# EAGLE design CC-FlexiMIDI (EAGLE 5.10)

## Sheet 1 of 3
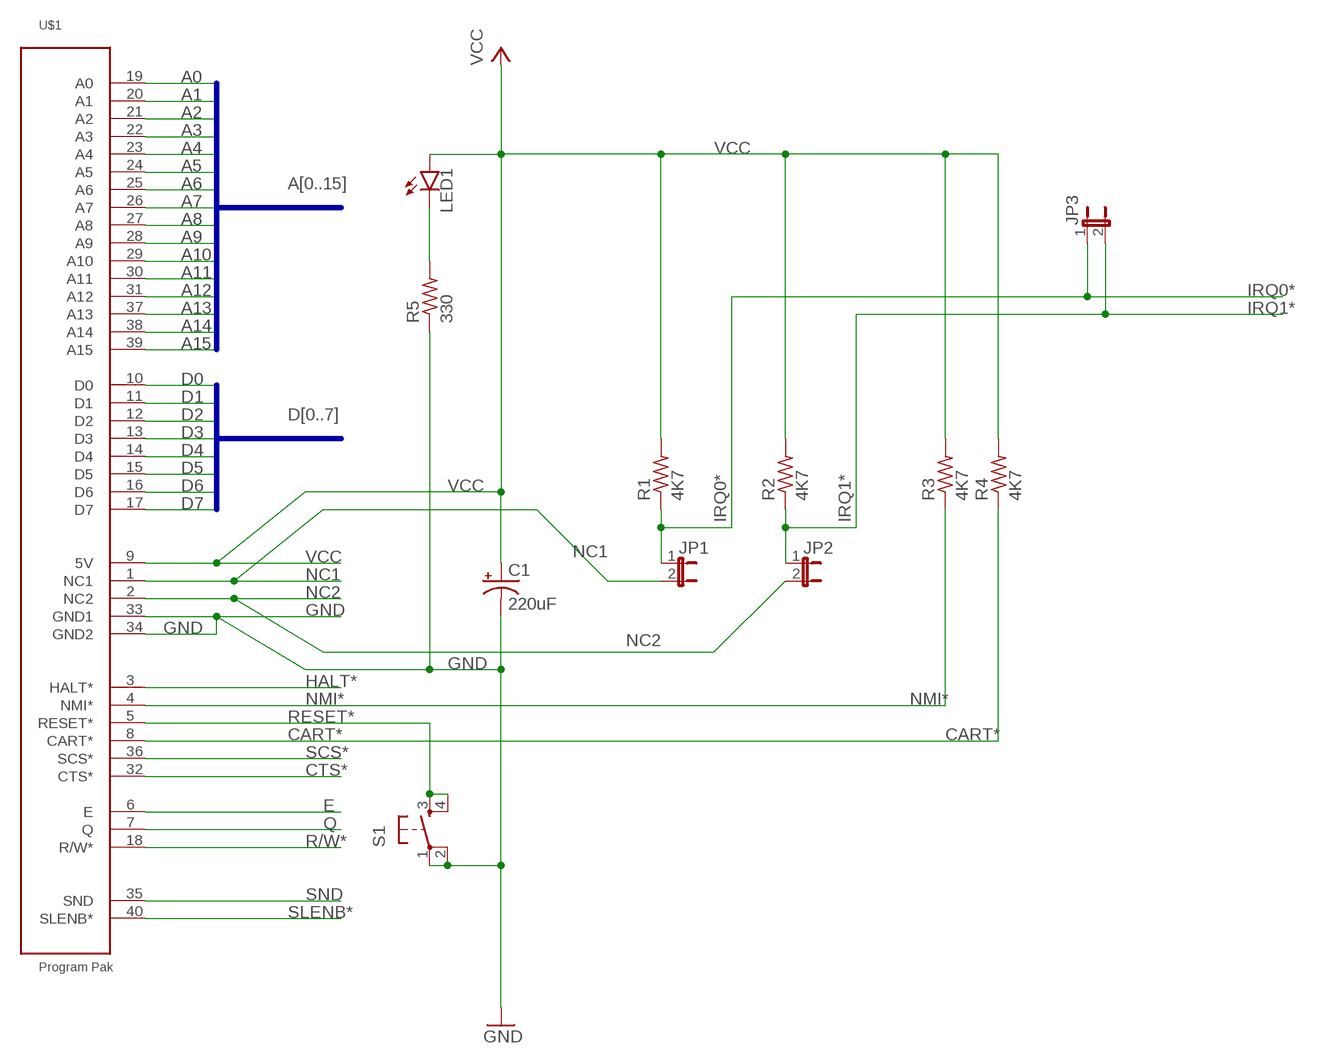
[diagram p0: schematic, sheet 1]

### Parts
C1  220uF  SPARKFUN_CAP_POLPTH1  [SPARKFUN_CPOL-RADIAL-100UF-25V]
JP1  JP1E  [JP1]
JP2  JP1E  [JP1]
JP3  JP1E  [JP1]
LED1  RED  LED5MM  [LED5MM]
R1  4K7  R-US_0207/7  [0207/7]
R2  4K7  R-US_0207/7  [0207/7]
R3  4K7  R-US_0207/7  [0207/7]
R4  4K7  R-US_0207/7  [0207/7]
R5  330  R-US_0207/7  [0207/7]
S1  RESET  TAC_SWITCHPTH  [TACTILE-PTH]
U$1  Program Pak  SERIALTECH_COCO_CARTRIDGE  [SERIALTECH_EDGE40]

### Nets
A0: U$1.19(A0) ; also sheet 3
A1: U$1.20(A1) ; also sheet 3
A2: U$1.21(A2) ; also sheet 3
A3: U$1.22(A3) ; also sheet 2
A4: U$1.23(A4) ; also sheet 2
A5: U$1.24(A5) ; also sheet 3
A6: U$1.25(A6) ; also sheet 3
A7: U$1.26(A7) ; also sheet 2
A8: U$1.27(A8) ; also sheet 3
A9: U$1.28(A9) ; also sheet 3
A10: U$1.29(A10) ; also sheet 3
A11: U$1.30(A11) ; also sheet 3
A12: U$1.31(A12) ; also sheet 3
A13: U$1.37(A13) ; also sheet 3
A14: U$1.38(A14) ; also sheet 3
A15: U$1.39(A15) ; also sheet 3
CART*: R4.1 U$1.8(CART*) ; also sheet 3
CTS*: U$1.32(CTS*)
D0: U$1.10(D0) ; also sheet 3
D1: U$1.11(D1) ; also sheet 3
D2: U$1.12(D2) ; also sheet 3
D3: U$1.13(D3) ; also sheet 3
D4: U$1.14(D4) ; also sheet 3
D5: U$1.15(D5) ; also sheet 3
D6: U$1.16(D6) ; also sheet 3
D7: U$1.17(D7) ; also sheet 3
E: U$1.6(E) ; also sheet 3
GND [power]: C1.2(-) R5.1 S1.1 S1.2 U$1.33(GND1) U$1.34(GND2) ; also sheet 2,3
HALT*: U$1.3(HALT*)
IRQ0*: JP1.1 JP3.1 R1.1 ; also sheet 3
IRQ1*: JP2.1 JP3.2 R2.1 ; also sheet 3
N$2: LED1.K(CATHODE) R5.2
NC1: JP1.2 U$1.1(NC1)
NC2: JP2.2 U$1.2(NC2)
NMI*: R3.1 U$1.4(NMI*) ; also sheet 3
Q: U$1.7(Q)
R/W*: U$1.18(R/W*) ; also sheet 3
RESET*: S1.3 S1.4 U$1.5(RESET*)
SCS*: U$1.36(SCS*)
SLENB*: U$1.40(SLENB*)
SND: U$1.35(SND)
VCC [power]: C1.1(+) LED1.A(ANODE) R1.2 R2.2 R3.2 R4.2 U$1.9(5V) ; also sheet 2,3

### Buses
A[0..15]
D[0..7]

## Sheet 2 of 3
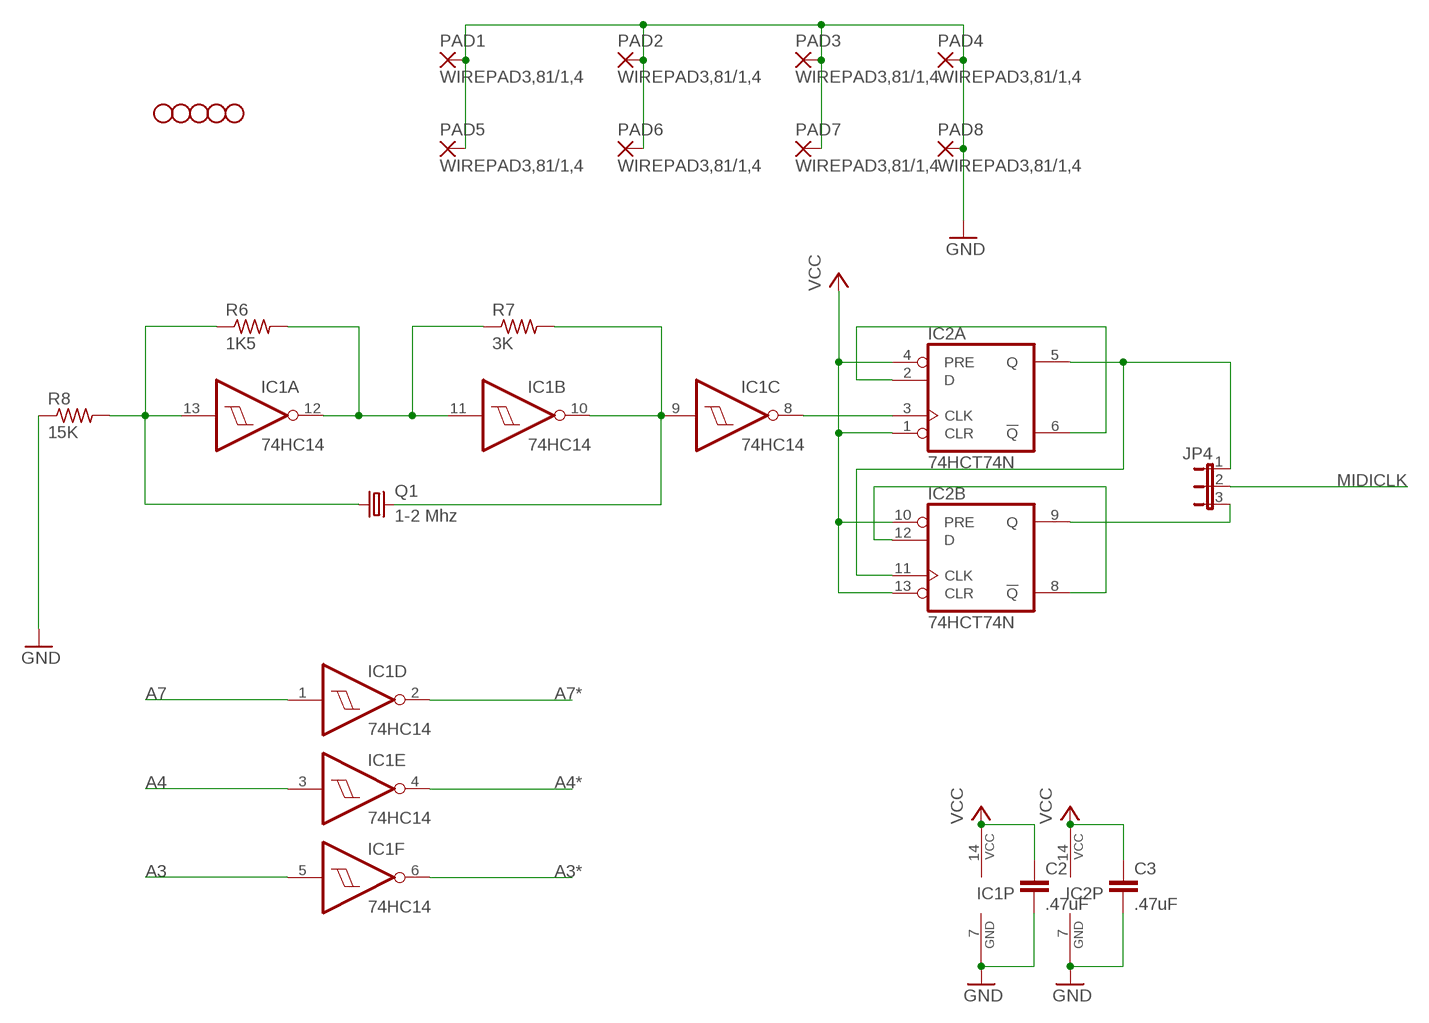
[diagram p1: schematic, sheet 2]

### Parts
C2  .47uF  C2.5/4  [C2.5-4]
C3  .47uF  C2.5/4  [C2.5-4]
IC1  74HC14  74LS14N  [DIL14]
IC2  74HCT74N  74LS74N  [DIL14]
JP4  JP2E  [JP2]
PAD1  WIREPAD3,81/1,4  [3,81/1,4]
PAD2  WIREPAD3,81/1,4  [3,81/1,4]
PAD3  WIREPAD3,81/1,4  [3,81/1,4]
PAD4  WIREPAD3,81/1,4  [3,81/1,4]
PAD5  WIREPAD3,81/1,4  [3,81/1,4]
PAD6  WIREPAD3,81/1,4  [3,81/1,4]
PAD7  WIREPAD3,81/1,4  [3,81/1,4]
PAD8  WIREPAD3,81/1,4  [3,81/1,4]
Q1  1-2 Mhz  CRYSTALHC49US  [HC49US]
R6  1K5  R-US_0207/7  [0207/7]
R7  3K  R-US_0207/7  [0207/7]
R8  15K  R-US_0207/7  [0207/7]
U$2  SPARKFUN_STAND-OFF  [SPARKFUN_STAND-OFF]
U$3  SPARKFUN_STAND-OFF  [SPARKFUN_STAND-OFF]
U$4  SPARKFUN_STAND-OFF  [SPARKFUN_STAND-OFF]
U$5  SPARKFUN_STAND-OFF  [SPARKFUN_STAND-OFF]
U$6  SPARKFUN_STAND-OFF  [SPARKFUN_STAND-OFF]

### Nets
A3: IC1.5(F:I) ; also sheet 1
A3*: IC1.6(F:O) ; also sheet 3
A4: IC1.3(E:I) ; also sheet 1
A4*: IC1.4(E:O) ; also sheet 3
A7: IC1.1(D:I) ; also sheet 1
A7*: IC1.2(D:O) ; also sheet 3
GND [power]: C2.2 C3.2 IC1.7(P:GND) IC2.7(P:GND) PAD1.1(P) PAD2.1(P) PAD3.1(P) PAD4.1(P) PAD5.1(P) PAD6.1(P) PAD7.1(P) PAD8.1(P) R8.1 ; also sheet 1,3
MIDICLK: JP4.2 ; also sheet 3
N$1: IC1.11(B:I) IC1.12(A:O) R6.2 R7.1
N$3: IC1.13(A:I) Q1.1 R6.1 R8.2
N$4: IC1.9(C:I) IC1.10(B:O) Q1.2 R7.2
N$5: IC2.2(A:D) IC2.6(A:!Q)
N$6: IC2.8(B:!Q) IC2.12(B:D)
N$7: IC2.5(A:Q) IC2.11(B:CLK) JP4.1
N$8: IC2.9(B:Q) JP4.3
N$9: IC1.8(C:O) IC2.3(A:CLK)
VCC [power]: C2.1 C3.1 IC1.14(P:VCC) IC2.1(A:CLR) IC2.4(A:PRE) IC2.10(B:PRE) IC2.13(B:CLR) IC2.14(P:VCC) ; also sheet 1,3

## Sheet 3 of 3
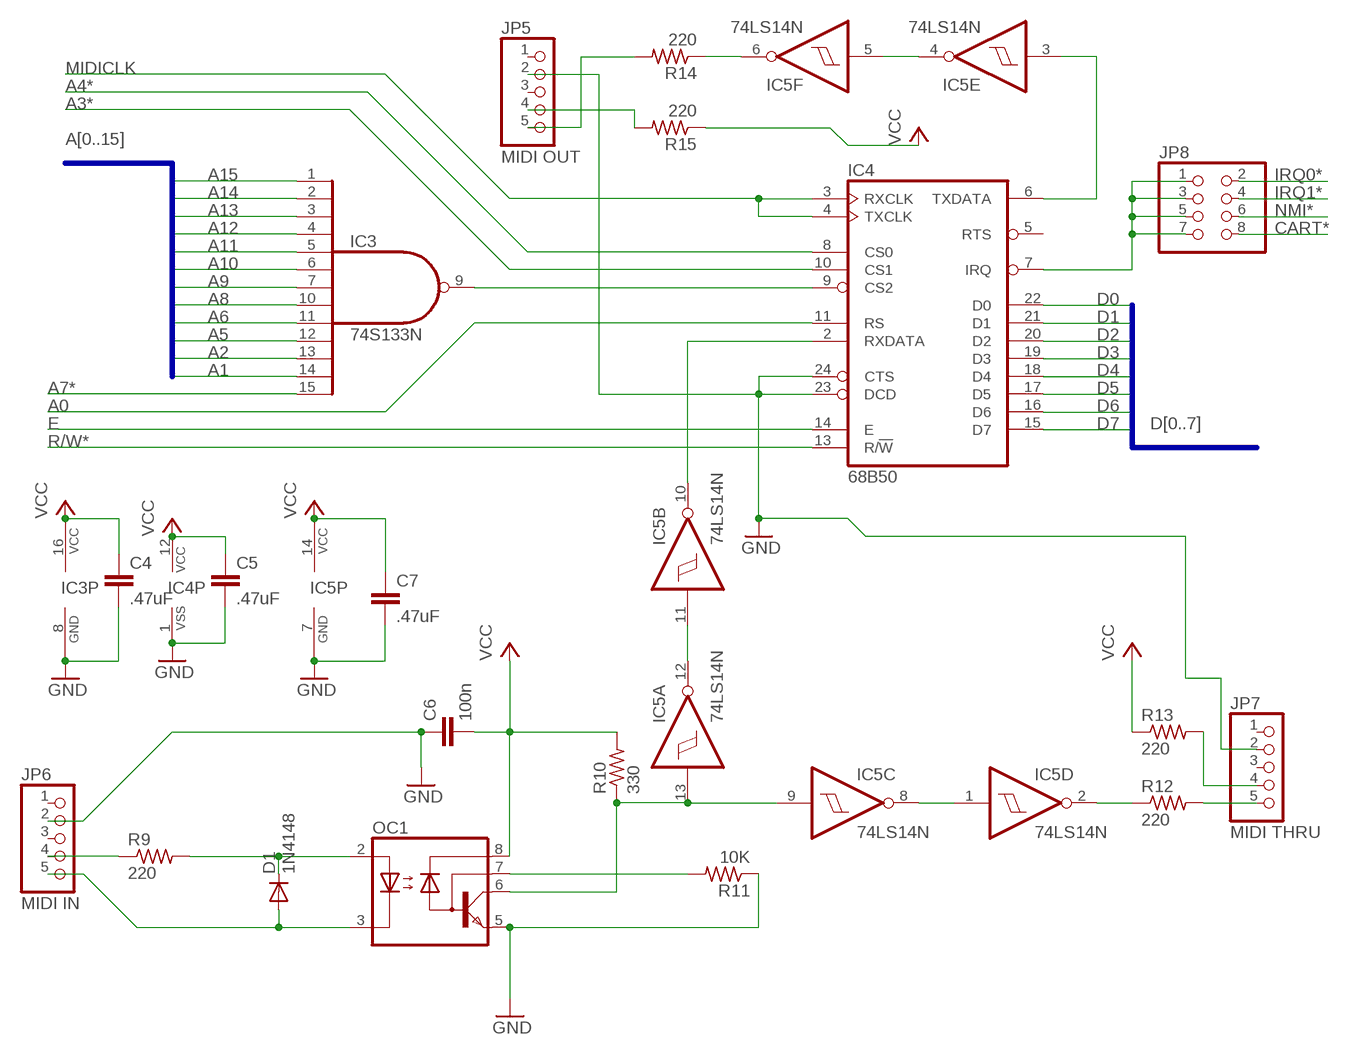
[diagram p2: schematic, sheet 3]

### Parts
C4  .47uF  C2.5/4  [C2.5-4]
C5  .47uF  C2.5/4  [C2.5-4]
C6  100n  C2.5/4  [C2.5-4]
C7  .47uF  C2.5/4  [C2.5-4]
D1  1N4148  [DO35-10]
IC3  74S133N  [DIL16]
IC4  68B50  6850  [DIL24]
IC5  74LS14N  [DIL14]
JP5  MIDI OUT  PINHD-1X5M  [1X05M]
JP6  MIDI IN  PINHD-1X5M  [1X05M]
JP7  MIDI THRU  PINHD-1X5M  [1X05M]
JP8  PINHD-2X4M  [2X04M]
OC1  6N139  [DIL08]
R9  220  R-US_0207/7  [0207/7]
R10  330  R-US_0207/7  [0207/7]
R11  10K  R-US_0207/7  [0207/7]
R12  220  R-US_0207/7  [0207/7]
R13  220  R-US_0207/7  [0207/7]
R14  220  R-US_0207/7  [0207/7]
R15  220  R-US_0207/7  [0207/7]

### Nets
A0: IC4.11(RS) ; also sheet 1
A1: IC3.14(I11) ; also sheet 1
A2: IC3.13(I10) ; also sheet 1
A3*: IC4.10(CS1) ; also sheet 2
A4*: IC4.8(CS0) ; also sheet 2
A5: IC3.12(I9) ; also sheet 1
A6: IC3.11(I8) ; also sheet 1
A7*: IC3.15(I12) ; also sheet 2
A8: IC3.10(I7) ; also sheet 1
A9: IC3.7(I6) ; also sheet 1
A10: IC3.6(I5) ; also sheet 1
A11: IC3.5(I4) ; also sheet 1
A12: IC3.4(I3) ; also sheet 1
A13: IC3.3(I2) ; also sheet 1
A14: IC3.2(I1) ; also sheet 1
A15: IC3.1(I0) ; also sheet 1
CART*: JP8.8 ; also sheet 1
D0: IC4.22(D0) ; also sheet 1
D1: IC4.21(D1) ; also sheet 1
D2: IC4.20(D2) ; also sheet 1
D3: IC4.19(D3) ; also sheet 1
D4: IC4.18(D4) ; also sheet 1
D5: IC4.17(D5) ; also sheet 1
D6: IC4.16(D6) ; also sheet 1
D7: IC4.15(D7) ; also sheet 1
E: IC4.14(E) ; also sheet 1
GND [power]: C4.2 C5.2 C6.1 C7.2 IC3.8(GND) IC4.1(VSS) IC4.23(DCD) IC4.24(CTS) IC5.7(P:GND) JP5.2 JP6.2 JP7.2 OC1.5(GND) R11.1 ; also sheet 1,2
IRQ0*: JP8.2 ; also sheet 1
IRQ1*: JP8.4 ; also sheet 1
MIDICLK: IC4.3(RXCLK) IC4.4(TXCLK) ; also sheet 2
N$10: IC3.9(O) IC4.9(CS2)
N$19: OC1.7(VB) R11.2
N$20: D1.C OC1.2(A) R9.2
N$21: D1.A JP6.5 OC1.3(C)
N$22: IC4.2(RXDATA) IC5.10(B:O)
N$23: IC5.9(C:I) IC5.13(A:I) OC1.6(VO) R10.1
N$24: IC5.1(D:I) IC5.8(C:O)
N$25: IC4.6(TXDATA) IC5.3(E:I)
N$26: IC5.4(E:O) IC5.5(F:I)
N$27: IC5.6(F:O) R14.1
N$28: JP5.5 R14.2
N$29: IC5.11(B:I) IC5.12(A:O)
N$30: JP6.4 R9.1
N$32: IC4.7(IRQ) JP8.1 JP8.3 JP8.5 JP8.7
N$33: IC5.2(D:O) R12.1
N$34: JP7.5 R12.2
N$35: JP7.4 R13.2
N$37: JP5.4 R15.2
NMI*: JP8.6 ; also sheet 1
R/W*: IC4.13(R/!W) ; also sheet 1
VCC [power]: C4.1 C5.1 C6.2 C7.1 IC3.16(VCC) IC4.12(VCC) IC5.14(P:VCC) OC1.8(VCC) R10.2 R13.1 R15.1 ; also sheet 1,2
Unconnected: IC4.5(RTS) JP5.1 JP5.3 JP6.1 JP6.3 JP7.1 JP7.3

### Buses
A[0..15]
D[0..7]

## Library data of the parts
C1 = FDC:SPARKFUN_CAP_POL: Capacitor Polarized
C2-C7 = capacitor-wima:C: CAPACITOR
D1 = diode:1N4148: DIODE
IC1 IC5 = 74xx-us:74*14: Hex schmitt trigger INVERTER
IC2 = 74xx-us:74*74: Dual D type positive edge triggered FLIP FLOP, preset and clear
IC3 = 74xx-us:74*133: 13-input NAND gate
IC4 = micro-motorola:6850: MICROCONTROLLER/MEMORY DEVICE
JP1-JP3 = jumper:JP1E: JUMPER
JP4 = jumper:JP2E: JUMPER
JP5-JP7 = pinhead:PINHD-1X5: PIN HEADER
JP8 = pinhead:PINHD-2X4: PIN HEADER
LED1 = tango:LED: LED
OC1 = optocoupler:6N139
PAD1-PAD8 = wirepad:WIREPAD: Wire PAD connect wire on PCB
Q1 = SparkFun-3-2-07:CRYSTAL: Crystals
R1-R15 = rcl-2:R-US_: RESISTOR, American symbol
S1 = SparkFunEagle-6-6-07:TAC_SWITCH: Momentary Switch Button commonly used for reset or general input. Spark Fun Electronics SKU : COM-00097
U$1 = FDC:SERIALTECH_COCO_CARTRIDGE
U$2-U$6 = FDC:SPARKFUN_STAND-OFF: Stand Off

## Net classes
0 default: width 0.254 mm, drill 0.508 mm, clearance 0.203 mm
1 power: width 0.762 mm, drill 0.508 mm, clearance 0.254 mm

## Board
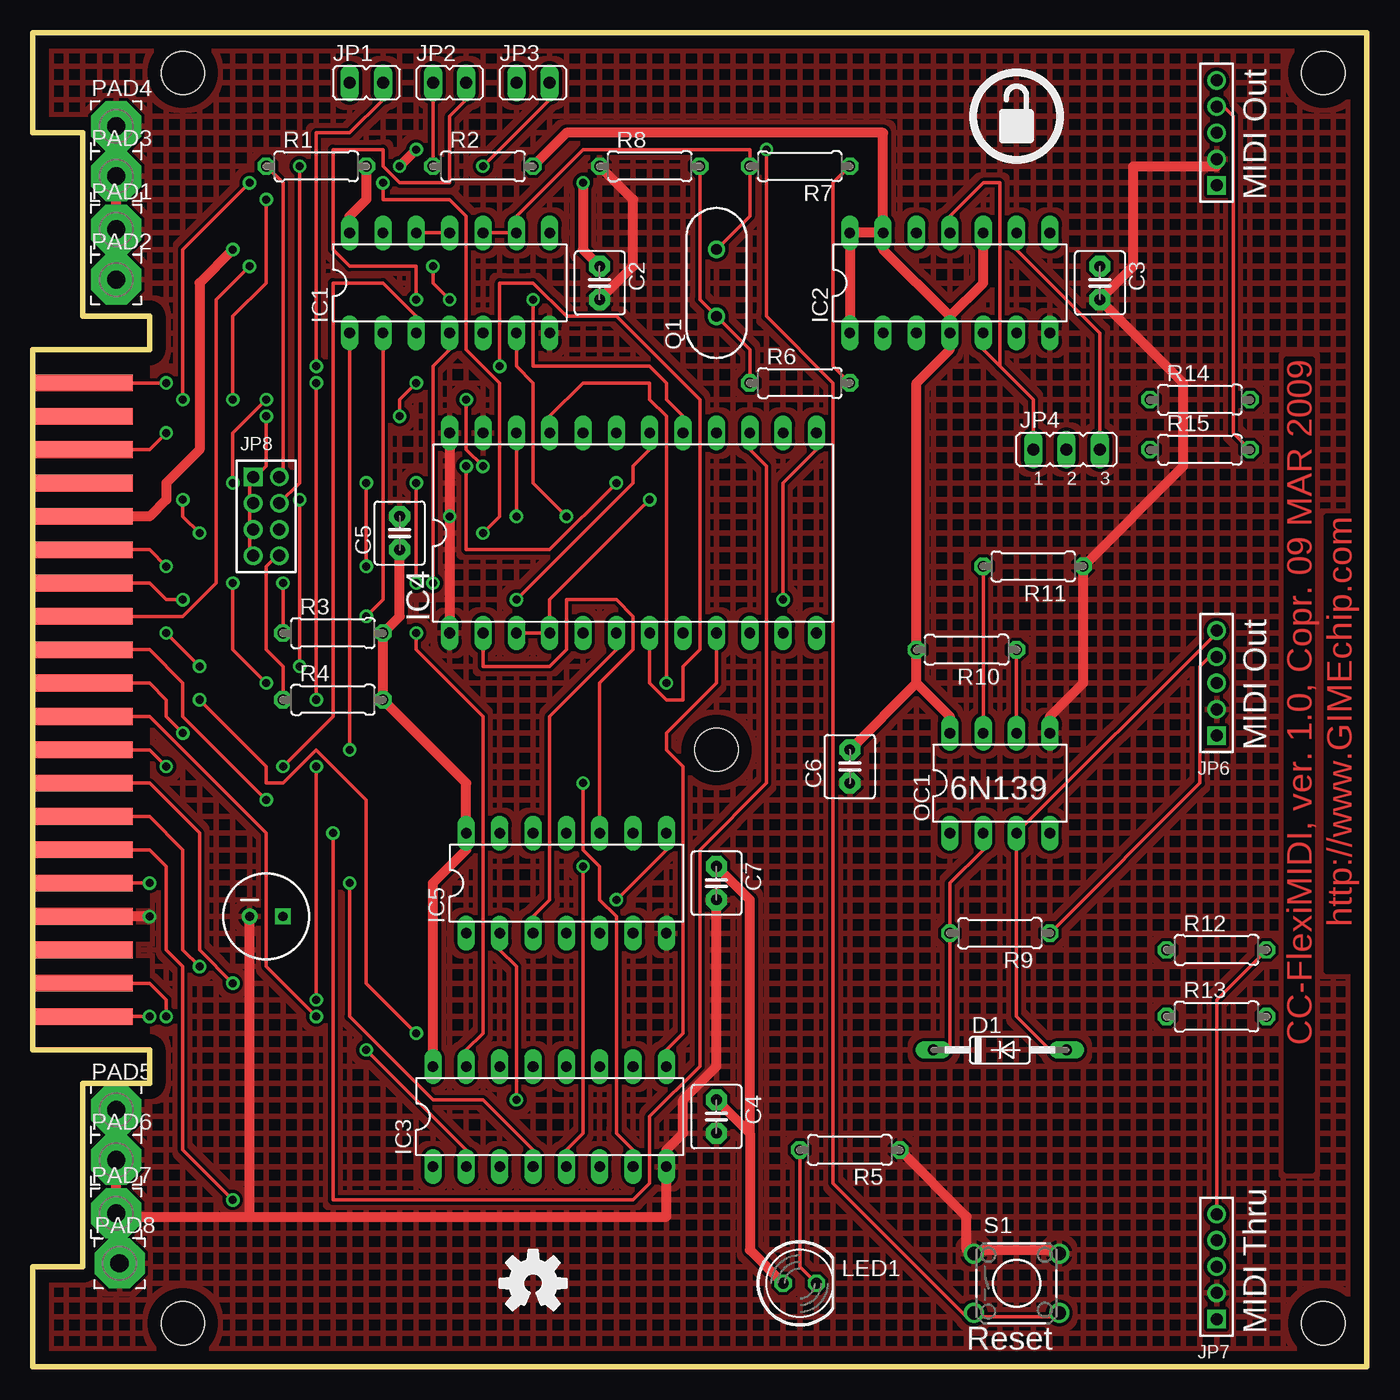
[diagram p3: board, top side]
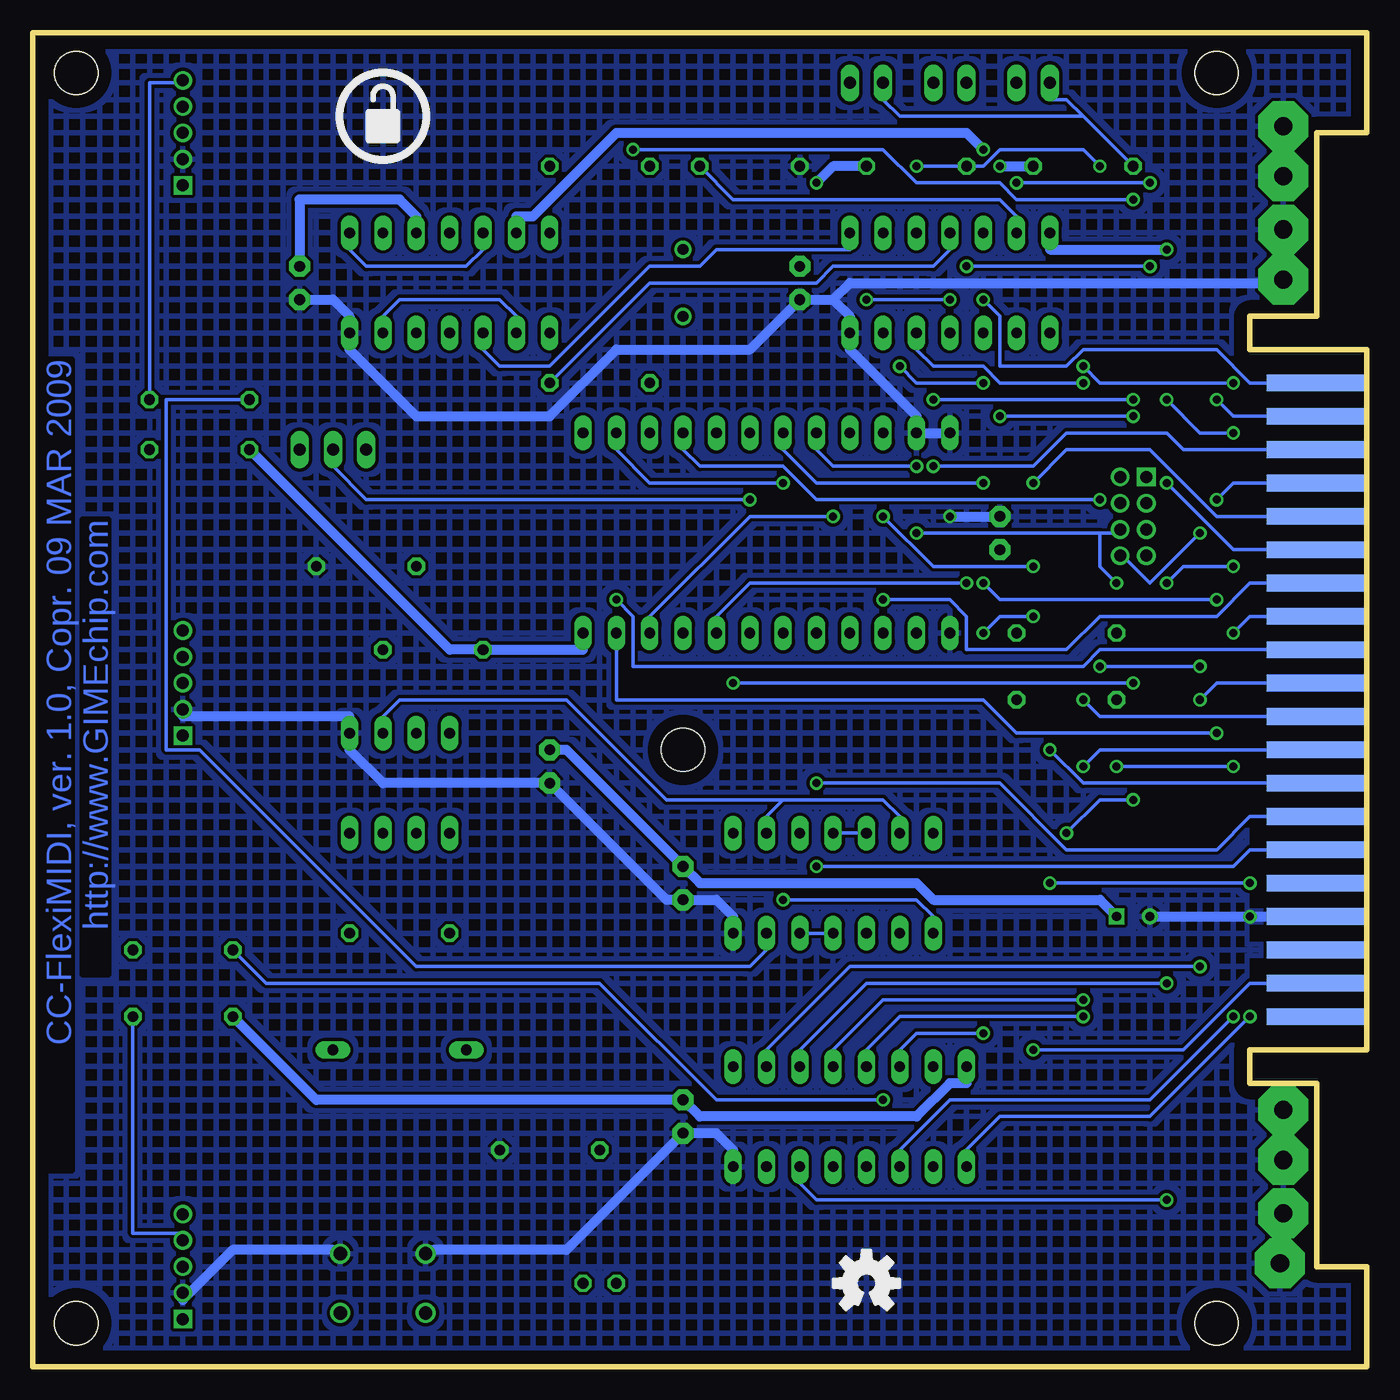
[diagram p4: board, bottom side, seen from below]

Size 101.6 x 101.6 mm. Coordinates in mm from the lower left corner, seen from the top.
Outline: 0,0 101.6,0 101.6,101.6 0,101.6 0,93.98 3.81,93.98 3.81,80.01 8.89,80.01 8.89,77.47 0,77.47 0,24.13 8.89,24.13 8.89,21.59 3.81,21.59 3.81,7.62 0,7.62 0,0
Copper layers (1*16): Top 0.035mm / dielectric 1.5mm / Bottom 0.035mm
Design rules "default": minimum track width 10mil, minimum drill 24mil, track to track 8mil, track to pad 8mil, pad to pad 8mil, via to via 8mil, smd to smd 8mil, copper to edge 40mil, drill to drill 8mil, minimum pad ring 10mil, minimum via ring 8mil, stop-mask expansion 4mil, vias tented up to drill 0mil, thermal gap 10mil

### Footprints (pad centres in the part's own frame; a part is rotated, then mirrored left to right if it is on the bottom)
SPARKFUN_CPOL-RADIAL-100UF-25V = drill 0.7 square: 1 1.27,0 | drill 0.7 round: 2 -1.27,0
C2.5-4 = drill 0.813 pad 1.6 octagon: 1 -1.27,0; 2 1.27,0
DO35-10 = drill 0.813 long: A 5.08,0; C -5.08,0
DIL14 = drill 0.813 long: 1 -7.62,-3.81; 2 -5.08,-3.81; 3 -2.54,-3.81; 4 0,-3.81; 5 2.54,-3.81; 6 5.08,-3.81; 7 7.62,-3.81; 8 7.62,3.81; 9 5.08,3.81; 10 2.54,3.81; 11 0,3.81; 12 -2.54,3.81; 13 -5.08,3.81; 14 -7.62,3.81
DIL16 = drill 0.813 long: 1 -8.89,-3.81; 2 -6.35,-3.81; 3 -3.81,-3.81; 4 -1.27,-3.81; 5 1.27,-3.81; 6 3.81,-3.81; 7 6.35,-3.81; 8 8.89,-3.81; 9 8.89,3.81; 10 6.35,3.81; 11 3.81,3.81; 12 1.27,3.81; 13 -1.27,3.81; 14 -3.81,3.81; 15 -6.35,3.81; 16 -8.89,3.81
DIL24 = drill 0.813 long: 1 -13.97,-7.62; 2 -11.43,-7.62; 3 -8.89,-7.62; 4 -6.35,-7.62; 5 -3.81,-7.62; 6 -1.27,-7.62; 7 1.27,-7.62; 8 3.81,-7.62; 9 6.35,-7.62; 10 8.89,-7.62; 11 11.43,-7.62; 12 13.97,-7.62; 13 13.97,7.62; 14 11.43,7.62; 15 8.89,7.62; 16 6.35,7.62; 17 3.81,7.62; 18 1.27,7.62; 19 -1.27,7.62; 20 -3.81,7.62; 21 -6.35,7.62; 22 -8.89,7.62; 23 -11.43,7.62; 24 -13.97,7.62
JP1 = drill 0.914 long: 1 0,-1.27; 2 0,1.27
JP2 = drill 0.914 long: 1 -2.54,0; 2 0,0; 3 2.54,0
1X05M = drill 0.914 square: 1 -4,0 | drill 0.914 round: 2 -2,0; 3 0,0; 4 2,0; 5 4,0
2X04M = drill 0.914 square: 1 -3,-1 | drill 0.914 round: 2 -3,1; 3 -1,-1; 4 -1,1; 5 1,-1; 6 1,1; 7 3,-1; 8 3,1
LED5MM = drill 0.813 octagon: A -1.27,0; K 1.27,0
DIL08 = drill 0.813 long: 1 -3.81,-3.81; 2 -1.27,-3.81; 3 1.27,-3.81; 4 3.81,-3.81; 5 3.81,3.81; 6 1.27,3.81; 7 -1.27,3.81; 8 -3.81,3.81
3,81/1,4 = drill 1.397 pad 3.81 octagon: 1 0,0
HC49US = drill 0.813 round: 1 -2.54,0; 2 2.54,0
0207/7 = drill 0.813 octagon: 1 -3.81,0; 2 3.81,0
TACTILE-PTH = drill 1.016 round: 1 -3.251,2.261; 2 3.251,2.261; 3 -3.251,-2.261; 4 3.251,-2.261
SERIALTECH_EDGE40 = smd 7.62 x 1.27: 1 0,24.13; 3 0,21.59; 5 0,19.05; 7 0,16.51; 9 0,13.97; 11 0,11.43; 13 0,8.89; 15 0,6.35; 17 0,3.81; 19 0,1.27; 21 0,-1.27; 23 0,-3.81; 25 0,-6.35; 27 0,-8.89; 29 0,-11.43; 31 0,-13.97; 33 0,-16.51; 35 0,-19.05; 37 0,-21.59; 39 0,-24.13 | smd 7.62 x 1.27 bottom: 2 0,24.13; 4 0,21.59; 6 0,19.05; 8 0,16.51; 10 0,13.97; 12 0,11.43; 14 0,8.89; 16 0,6.35; 18 0,3.81; 20 0,1.27; 22 0,-1.27; 24 0,-3.81; 26 0,-6.35; 28 0,-8.89; 30 0,-11.43; 32 0,-13.97; 34 0,-16.51; 36 0,-19.05; 38 0,-21.59; 40 0,-24.13
SPARKFUN_STAND-OFF = hole 3.302: 0,0

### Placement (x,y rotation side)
C1  17.78,34.29 0 top
C2  43.18,82.55 270 top
C3  81.28,82.55 270 top
C4  52.07,19.05 270 top
C5  27.94,63.5 90 top
C6  62.23,45.72 90 top
C7  52.07,36.83 270 top
D1  73.66,24.13 0 top
IC1  31.75,82.55 0 top
IC2  69.85,82.55 0 top
IC3  39.37,19.05 0 top
IC4  45.72,63.5 0 top
IC5  40.64,36.83 0 top
JP1  25.4,97.79 270 top
JP2  31.75,97.79 270 top
JP3  38.1,97.79 270 top
JP4  78.74,69.85 0 top
JP5  90.17,93.98 90 top
JP6  90.17,52.07 90 top
JP7  90.17,7.62 90 top
JP8  17.78,64.77 270 top
LED1  58.42,6.35 0 top
OC1  73.66,44.45 0 top
PAD1  6.35,86.61 0 top
PAD2  6.35,82.8 0 top
PAD3  6.35,90.68 0 top
PAD4  6.35,94.49 0 top
PAD5  6.35,19.56 0 top
PAD6  6.35,15.75 0 top
PAD7  6.35,11.68 0 top
PAD8  6.6,7.87 0 top
Q1  52.07,82.55 90 top
R1  21.59,91.44 0 top
R2  34.29,91.44 0 top
R3  22.86,55.88 0 top
R4  22.86,50.8 0 top
R5  62.23,16.51 180 top
R6  58.42,74.93 0 top
R7  58.42,91.44 180 top
R8  46.99,91.44 0 top
R9  73.66,33.02 180 top
R10  71.12,54.61 180 top
R11  76.2,60.96 180 top
R12  90.17,31.75 0 top
R13  90.17,26.67 0 top
R14  88.9,73.66 0 top
R15  88.9,69.85 0 top
S1  74.93,6.35 0 top
U$1  3.81,50.8 0 top
U$2  11.43,98.55 0 top
U$3  11.43,3.3 0 top
U$4  52.07,46.99 0 top
U$5  98.3,98.55 0 top
U$6  98.3,3.3 0 top
U$7  [OSHWLOGO_0.3]  74.93,95.25 0 top
U$8  [OSHWLOGO_0.3]  74.93,95.25 0 bottom
U$9  [OSHWLOGO_TOL_0.2]  38.1,6.35 0 top
U$10  [OSHWLOGO_TOL_0.2]  38.1,6.35 0 bottom

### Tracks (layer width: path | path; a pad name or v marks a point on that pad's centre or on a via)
A0  (via drill 0.61)
  Top 0.254: v11.43,48.26 10.16,49.53 10.16,50.8 8.89,52.07 U$1.19
  Bottom 0.254: v11.43,48.26 26.67,48.26 29.21,50.8 57.15,50.8 IC4.11
A1  (via drill 0.61)
  Top 0.254: v29.21,25.4 25.4,29.21 25.4,43.18 21.59,46.99 19.05,44.45 17.78,44.45 17.78,45.72 v12.7,50.8
  Bottom 0.254: v29.21,25.4 34.29,25.4 35.56,24.13 IC3.14 | v12.7,50.8 11.43,52.07 U$1.20
A2  (via drill 0.61)
  Top 0.254: v21.59,26.67 17.78,30.48 17.78,40.64 8.89,49.53 U$1.21
  Bottom 0.254: v21.59,26.67 35.56,26.67 38.1,24.13 IC3.13
A3  (via drill 0.61)
  Top 0.254: v21.59,50.8 v21.59,74.93
  Bottom 0.254: v21.59,74.93 27.94,74.93 29.21,76.2 33.02,76.2 34.29,77.47 IC1.5 | v21.59,50.8 20.32,49.53 U$1.22
A3*  (via drill 0.61)
  Top 0.254: v40.64,64.77 38.1,67.31 38.1,74.93 36.83,76.2 IC1.6
  Bottom 0.254: v40.64,64.77 46.99,64.77 54.61,57.15 IC4.10
A4  (via drill 0.61)
  Top 0.254: v19.05,45.72 22.86,49.53 22.86,82.55 26.67,82.55 29.21,80.01 IC1.3 | v10.16,45.72 8.89,46.99 U$1.23
  Bottom 0.254: v10.16,45.72 v19.05,45.72
A4*  (via drill 0.61)
  Top 0.254: v30.48,59.69 30.48,76.2 31.75,77.47 IC1.4
  Bottom 0.254: v30.48,59.69 46.99,59.69 49.53,57.15 IC4.8
A5  (via drill 0.61)
  Top 0.254: v21.59,27.94 v21.59,45.72
  Bottom 0.254: v21.59,27.94 36.83,27.94 40.64,24.13 IC3.12 | v21.59,45.72 20.32,46.99 U$1.24
A6  (via drill 0.61)
  Top 0.254: v15.24,29.21 12.7,31.75 12.7,40.64 8.89,44.45 U$1.25
  Bottom 0.254: v15.24,29.21 38.1,29.21 43.18,24.13 IC3.11
A7  (via drill 0.61)
  Top 0.254: v24.13,46.99 IC1.1
  Bottom 0.254: v24.13,46.99 21.59,44.45 U$1.26
A7*  (via drill 0.61)
  Top 0.254: v29.21,55.88 29.21,54.61 34.29,49.53 34.29,25.4 33.02,24.13 IC3.15 | v25.4,57.15 26.67,58.42 IC1.2
  Bottom 0.254: v29.21,55.88 27.94,57.15 v25.4,57.15
A8  (via drill 0.61)
  Top 0.254: v12.7,30.48 11.43,31.75 11.43,39.37 8.89,41.91 U$1.27
  Bottom 0.254: v12.7,30.48 39.37,30.48 45.72,24.13 IC3.10
A9  (via drill 0.61)
  Top 0.254: v41.91,44.45 41.91,39.37 43.18,38.1 43.18,35.56 44.45,34.29 44.45,17.78 45.72,16.51 IC3.7
  Bottom 0.254: v41.91,44.45 27.94,44.45 22.86,39.37 11.43,39.37 8.89,41.91 U$1.28
A10  (via drill 0.61)
  Top 0.254: v15.24,12.7 11.43,16.51 11.43,30.48 10.16,31.75 10.16,38.1 8.89,39.37 U$1.29
  Bottom 0.254: v15.24,12.7 41.91,12.7 43.18,13.97 IC3.6
A11  (via drill 0.61)
  Top 0.254: v41.91,38.1 41.91,17.78 40.64,16.51 IC3.5
  Bottom 0.254: v41.91,38.1 10.16,38.1 8.89,39.37 U$1.30
A12  (via drill 0.61)
  Top 0.254: v24.13,36.83 24.13,26.67 30.48,20.32 34.29,20.32 38.1,16.51 IC3.4 | U$1.31 v8.89,36.83
  Bottom 0.254: v8.89,36.83 v24.13,36.83
A13  (via drill 0.61)
  Top 0.254: v10.16,26.67 10.16,27.94 8.89,29.21 U$1.37
  Bottom 0.254: v10.16,26.67 16.51,20.32 31.75,20.32 35.56,16.51 IC3.3
A14  (via drill 0.61)
  Top 0.254: v25.4,24.13 33.02,16.51 IC3.2
  Bottom 0.254: v25.4,24.13 13.97,24.13 8.89,29.21 U$1.38
A15  (via drill 0.61)
  Top 0.254: U$1.39 v8.89,26.67
  Bottom 0.254: v8.89,26.67 16.51,19.05 27.94,19.05 30.48,16.51 IC3.1
CART*  (via drill 0.61)
  Top 0.254: R4.1 19.05,53.34 17.78,54.61 17.78,60.96 19.05,62.23 JP8.8 | v12.7,63.5 11.43,64.77 v11.43,66.04
  Bottom 0.254: v12.7,63.5 16.51,59.69 19.05,62.23 JP8.8 | v11.43,66.04 10.16,67.31 U$1.8
D0  (via drill 0.61)
  Top 0.254: v25.4,67.31 v25.4,60.96 | v36.83,64.77 IC4.22
  Bottom 0.254: v36.83,64.77 33.02,60.96 v25.4,60.96 | v25.4,67.31 22.86,69.85 16.51,69.85 11.43,64.77 U$1.10
D1  (via drill 0.61)
  Top 0.254: v48.26,52.07 48.26,72.39 46.99,73.66 46.99,74.93 41.91,74.93 39.37,72.39 IC4.21 | v17.78,52.07 15.24,54.61 v15.24,59.69 | v10.16,60.96 8.89,62.23 U$1.11
  Bottom 0.254: v17.78,52.07 v48.26,52.07 | v15.24,59.69 13.97,60.96 v10.16,60.96
D2  (via drill 0.61)
  Top 0.254: v34.29,68.58 33.02,69.85 v33.02,73.66 | v17.78,73.66 15.24,71.12 v15.24,67.31
  Bottom 0.254: v34.29,68.58 40.64,68.58 41.91,69.85 IC4.20 | v17.78,73.66 v33.02,73.66 | v15.24,67.31 10.16,62.23 U$1.12
D3  (via drill 0.61)
  Top 0.254: v29.21,59.69 v29.21,67.31 | v11.43,58.42 10.16,58.42 8.89,59.69 U$1.13
  Bottom 0.254: v29.21,67.31 41.91,67.31 44.45,69.85 IC4.19 | v29.21,59.69 27.94,58.42 v11.43,58.42
D4  (via drill 0.61)
  Top 0.254: v36.83,58.42 45.72,67.31 45.72,68.58 46.99,69.85 IC4.18
  Bottom 0.254: v36.83,58.42 31.75,58.42 30.48,57.15 30.48,54.61 22.86,54.61 20.32,57.15 11.43,57.15 8.89,59.69 U$1.14
D5  (via drill 0.61)
  Top 0.254: v38.1,81.28 38.1,76.2 46.99,76.2 48.26,74.93 48.26,73.66 49.53,72.39 IC4.17 | v31.75,81.28 30.48,82.55 v30.48,83.82 | v16.51,83.82 13.97,81.28 13.97,59.69 11.43,57.15 U$1.15
  Bottom 0.254: v31.75,81.28 v38.1,81.28 | v16.51,83.82 v30.48,83.82
D6  (via drill 0.61)
  Top 0.254: v20.32,53.34 v20.32,66.04 | v10.16,55.88 v12.7,53.34
  Bottom 0.254: v20.32,66.04 41.91,66.04 44.45,68.58 50.8,68.58 52.07,69.85 IC4.16 | v12.7,53.34 v20.32,53.34 | v10.16,55.88 8.89,57.15 U$1.16
D7  (via drill 0.61)
  Top 0.254: v22.86,40.64 22.86,12.7 45.72,12.7 46.99,13.97 46.99,19.05 50.8,22.86 50.8,39.37 55.88,44.45 55.88,68.58 54.61,69.85 IC4.15 | v17.78,43.18 11.43,49.53 11.43,52.07 8.89,54.61 U$1.17
  Bottom 0.254: v22.86,40.64 20.32,43.18 v17.78,43.18
E  (via drill 0.61)
  Top 0.254: v44.45,67.31 39.37,62.23 33.02,62.23 v33.02,68.58
  Bottom 0.254: v44.45,67.31 54.61,67.31 57.15,69.85 IC4.14 | v33.02,68.58 25.4,68.58 22.86,71.12 15.24,71.12 13.97,69.85 U$1.6
GND  (via drill 0.61)
  Top 0.762: v8.89,34.29 U$1.34 | PAD7.1 PAD6.1 PAD5.1 | PAD8.1 6.35,8.89 PAD7.1 | 16.51,11.43 C1.2 | 16.51,11.43 7.62,11.43 PAD7.1 | R5.1 71.12,11.43 71.12,8.89 S1.1 72.39,8.89 77.47,8.89 S1.2 | 16.51,11.43 48.26,11.43 IC3.8 48.26,16.51 49.53,17.78 49.53,20.32 52.07,22.86 C7.2 | PAD2.1 PAD1.1 PAD3.1 PAD4.1 | R8.1 45.72,88.9 45.72,83.82 C2.2 | IC4.1 v31.75,64.77 IC4.24 | JP5.2 90.17,91.44 83.82,91.44 83.82,83.82 C3.2 87.63,74.93 87.63,68.58 R11.1 80.01,52.07 77.47,49.53 OC1.5
  Bottom 0.762: C1.2 v8.89,34.29 U$1.34 | JP7.2 90.17,5.08 86.36,8.89 78.74,8.89 S1.2 | IC3.8 48.26,16.51 49.53,17.78 C4.2 60.96,8.89 71.12,8.89 S1.1 | 40.64,81.28 39.37,80.01 IC1.7 39.37,77.47 34.29,72.39 IC4.23 IC4.24 | 40.64,81.28 C2.2 46.99,77.47 57.15,77.47 62.23,72.39 72.39,72.39 77.47,77.47 IC2.7 77.47,80.01 78.74,81.28 C3.2 | v31.75,64.77 C5.2 | 40.64,81.28 39.37,82.55 7.62,82.55 PAD2.1 | JP6.2 90.17,49.53 77.47,49.53 OC1.5 77.47,46.99 74.93,44.45 C6.1 53.34,35.56 C7.2 49.53,35.56 48.26,34.29 IC5.7
  pour Bottom (hatched): 0,101.6 101.6,101.6 101.6,0 0,0
  pour Top (hatched): 0,101.6 101.6,101.6 101.6,0 0,0
IRQ0*
  Top 0.254: R1.1 19.05,90.17 19.05,67.31 JP8.2
  Bottom 0.254: 21.59,95.25 22.86,96.52 24.13,96.52 JP1.1 | R1.1 21.59,95.25 | 21.59,95.25 35.56,95.25 36.83,96.52 JP3.1
IRQ1*  (via drill 0.61)
  Top 0.254: R2.1 JP2.1 | v20.32,91.44 20.32,67.31 JP8.4 | v34.29,91.44 39.37,96.52 JP3.2
  Bottom 0.254: v20.32,91.44 21.59,92.71 27.94,92.71 29.21,91.44 R2.1 v34.29,91.44
MIDICLK  (via drill 0.61)
  Top 0.254: IC4.3 IC4.4 39.37,58.42 v46.99,66.04
  Bottom 0.254: v46.99,66.04 76.2,66.04 78.74,68.58 JP4.2
N$1
  Top 0.254: IC1.12 IC1.11 | R6.2 60.96,76.2 60.96,90.17 R7.1
  Bottom 0.254: R6.2 54.61,82.55 41.91,82.55 40.64,83.82 33.02,83.82 31.75,85.09 IC1.11
N$2
  Top 0.254: LED1.K 58.42,7.62 R5.2
N$3
  Top 0.254: R6.1 54.61,77.47 Q1.1 50.8,81.28 R8.2
  Bottom 0.254: R8.2 48.26,88.9 27.94,88.9 26.67,87.63 IC1.13
N$4
  Top 0.254: IC1.10 IC1.9 36.83,87.63 41.91,92.71 54.61,92.71 R7.2 54.61,87.63 Q1.2
N$5
  Bottom 0.254: IC2.2 64.77,80.01 66.04,81.28 73.66,81.28 74.93,80.01 IC2.6
N$6
  Bottom 0.254: IC2.12 67.31,85.09 68.58,83.82 76.2,83.82 77.47,85.09 IC2.8
N$7
  Top 0.254: 73.66,76.2 76.2,73.66 JP4.1 | 73.66,76.2 72.39,77.47 IC2.5 | 73.66,76.2 73.66,90.17 72.39,90.17 69.85,87.63 IC2.11
N$8
  Top 0.254: IC2.9 74.93,85.09 81.28,78.74 JP4.3
N$9
  Bottom 0.254: IC1.8 39.37,85.09 49.53,85.09 50.8,83.82 54.61,83.82 62.23,76.2 66.04,76.2 67.31,77.47 IC2.3
N$10
  Top 0.254: IC3.9 48.26,24.13 49.53,25.4 49.53,45.72 48.26,46.99 48.26,48.26 52.07,52.07 IC4.9
N$19
  Top 0.254: OC1.7 R11.2
N$20
  Top 0.254: D1.C 69.85,24.13 R9.2 69.85,36.83 72.39,39.37 OC1.2
N$21
  Top 0.254: D1.A 77.47,24.13 74.93,26.67 OC1.3 90.17,55.88 JP6.5
N$22
  Top 0.254: IC5.10 43.18,52.07 45.72,54.61 45.72,57.15 44.45,58.42 40.64,58.42 40.64,54.61 39.37,53.34 34.29,53.34 IC4.2
N$23
  Top 0.254: OC1.6 R10.1
  Bottom 0.254: 44.45,43.18 36.83,43.18 35.56,41.91 IC5.13 | 44.45,43.18 45.72,41.91 IC5.9 | 44.45,43.18 53.34,43.18 60.96,50.8 73.66,50.8 74.93,49.53 OC1.6
N$24  (via drill 0.61)
  Top 0.254: v44.45,35.56 48.26,39.37 IC5.8
  Bottom 0.254: v44.45,35.56 34.29,35.56 33.02,34.29 IC5.1
N$25
  Top 0.254: IC5.3 38.1,34.29 39.37,35.56 39.37,49.53 44.45,54.61 IC4.6
N$26
  Bottom 0.254: IC5.4 IC5.5
N$27
  Bottom 0.254: R14.1 91.44,73.66 91.44,46.99 88.9,46.99 72.39,30.48 46.99,30.48 45.72,31.75 IC5.6
N$28
  Bottom 0.254: R14.2 92.71,97.79 90.17,97.79 JP5.5
N$29
  Bottom 0.254: IC5.12 IC5.11
N$30
  Top 0.254: R9.1 88.9,44.45 88.9,53.34 90.17,54.61 JP6.4
N$32  (via drill 0.61)
  Top 0.254: 16.51,63.5 16.51,62.23 JP8.7 | v35.56,76.2 35.56,82.55 38.1,82.55 40.64,80.01 44.45,80.01 50.8,73.66 50.8,54.61 49.53,53.34 49.53,50.8 48.26,50.8 46.99,52.07 IC4.7 | v29.21,74.93 27.94,73.66 v27.94,72.39 | v17.78,72.39 17.78,68.58 16.51,67.31 | 16.51,66.04 16.51,67.31 | 16.51,67.31 JP8.1 | 16.51,63.5 16.51,66.04 | 16.51,63.5 JP8.5 | 16.51,66.04 JP8.3
  Bottom 0.254: v35.56,76.2 34.29,74.93 v29.21,74.93 | v17.78,72.39 v27.94,72.39
N$33  (via drill 0.61)
  Top 0.254: v36.83,20.32 36.83,30.48 35.56,31.75 IC5.2
  Bottom 0.254: v36.83,20.32 49.53,20.32 58.42,29.21 83.82,29.21 R12.1
N$34
  Top 0.254: R12.2 90.17,27.94 JP7.5 90.17,11.43
N$35
  Bottom 0.254: R13.2 93.98,10.16 90.17,10.16 JP7.4
N$37
  Top 0.254: R15.2 91.44,71.12 91.44,95.25 90.17,96.52 JP5.4
NC1  (via drill 0.61)
  Top 0.254: v21.59,76.2 21.59,93.98 24.13,93.98 26.67,96.52 JP1.2 | U$1.1 v10.16,74.93
  Bottom 0.254: v21.59,76.2 20.32,74.93 v10.16,74.93
NC2  (via drill 0.61)
  Top 0.254: v29.21,81.28 29.21,83.82 24.13,83.82 22.86,85.09 22.86,92.71 26.67,92.71 26.67,91.44 27.94,90.17 31.75,90.17 31.75,95.25 33.02,96.52 JP2.2
  Bottom 0.254: v29.21,81.28 27.94,80.01 27.94,76.2 22.86,76.2 21.59,77.47 11.43,77.47 8.89,74.93 U$1.2
NMI*  (via drill 0.61)
  Top 0.254: R3.1 v19.05,59.69 | v34.29,63.5 35.56,64.77 35.56,74.93 33.02,77.47 33.02,87.63 31.75,88.9 26.67,88.9 v26.67,90.17 | v16.51,90.17 11.43,85.09 v11.43,73.66
  Bottom 0.254: v19.05,59.69 20.32,60.96 20.32,63.5 | 20.32,63.5 19.05,63.5 JP8.6 | 20.32,63.5 v34.29,63.5 | v26.67,90.17 v16.51,90.17 | v11.43,73.66 10.16,72.39 U$1.4
R/W*  (via drill 0.61)
  Top 0.254: v57.15,58.42 57.15,67.31 59.69,69.85 IC4.13
  Bottom 0.254: v57.15,58.42 55.88,57.15 55.88,53.34 21.59,53.34 20.32,54.61 U$1.18
RESET*  (via drill 0.61)
  Top 0.254: S1.4 77.47,3.81 72.39,3.81 S1.3 71.12,3.81 60.96,13.97 60.96,74.93 55.88,80.01 v55.88,92.71 | v17.78,88.9 17.78,82.55 15.24,80.01 v15.24,73.66 | v10.16,71.12 8.89,69.85 U$1.5
  Bottom 0.254: v55.88,92.71 36.83,92.71 34.29,90.17 27.94,90.17 26.67,88.9 v17.78,88.9 | v15.24,73.66 12.7,71.12 v10.16,71.12
VCC  (via drill 0.61)
  Top 0.762: R1.2 25.4,88.9 24.13,87.63 IC1.14 | v15.24,85.09 12.7,82.55 12.7,69.85 10.16,67.31 10.16,66.04 8.89,64.77 U$1.9 | 69.85,80.01 72.39,82.55 IC2.10 | IC2.1 IC2.14 IC2.13 | R2.2 40.64,93.98 64.77,93.98 IC2.13 | C2.1 41.91,85.09 v41.91,90.17 | 69.85,80.01 64.77,85.09 IC2.13 | 69.85,80.01 IC2.4 69.85,77.47 67.31,74.93 R10.2 67.31,52.07 | v29.21,92.71 v27.94,91.44 | 67.31,52.07 69.85,49.53 OC1.8 | C6.2 67.31,52.07 | C5.1 27.94,57.15 R3.2 R4.2 33.02,44.45 IC5.14 33.02,39.37 30.48,36.83 IC3.16 | LED1.A 54.61,8.89 54.61,17.78 | C4.1 54.61,17.78 | C7.1 54.61,35.56 54.61,17.78
  Bottom 0.762: v15.24,85.09 24.13,85.09 IC1.14 | C3.1 81.28,88.9 73.66,88.9 72.39,87.63 IC2.10 | v41.91,90.17 40.64,91.44 R2.2 | v27.94,91.44 R1.2 | v29.21,92.71 30.48,93.98 57.15,93.98 63.5,87.63 64.77,87.63 IC2.13 | C1.1 20.32,35.56 33.02,35.56 34.29,36.83 50.8,36.83 C7.1 60.96,46.99 C6.2 | IC4.12 59.69,54.61 R10.2 69.85,54.61 R15.1 | R13.1 80.01,20.32 C4.1 50.8,19.05 34.29,19.05 31.75,21.59 30.48,21.59 IC3.16

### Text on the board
Top: CC-FlexiMIDI, ver. 1.0, Copr. 09 MAR 2009 | http://www.GIMEchip.com
Bottom: CC-FlexiMIDI, ver. 1.0, Copr. 09 MAR 2009 | http://www.GIMEchip.com
tPlace: MIDI Out | MIDI Out | 6N139 | MIDI Thru | Reset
